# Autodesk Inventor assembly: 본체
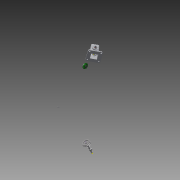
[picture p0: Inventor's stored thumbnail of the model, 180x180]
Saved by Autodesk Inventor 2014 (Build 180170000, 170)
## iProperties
Created: 2016-02
Part Number: 본체
Document SubType Name: Assembly
Designer: user
Author: user
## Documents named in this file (15)
- C:\Users\user\Desktop\460212V1001\본체.iam
- C:\Users\user\Desktop\460212V1001\본체1.ipt
- C:\Users\user\Desktop\460212V1001\편심축.ipt
- C:\Users\user\Desktop\460212V1001\V벨트풀리.ipt
- C:\Users\user\Desktop\460212V1001\고정핀 1.2 x 10.ipt
- C:\Users\user\Desktop\460212V1001\링크.ipt
- C:\Users\user\Desktop\460212V1001\멈춤나사 M3x8.ipt
- C:\Users\user\Desktop\460212V1001\베어링 12 x 32 x 10.ipt
- C:\Users\user\Desktop\460212V1001\볼트 M4 x 12.ipt
- C:\Users\user\Desktop\460212V1001\부시.ipt
- C:\Users\user\Desktop\460212V1001\슬라이드.ipt
- C:\Users\user\Desktop\460212V1001\앞커버.ipt
- C:\Users\user\Desktop\460212V1001\오일실 12 25 7.ipt
- C:\Users\user\Desktop\460212V1001\키 4 x 4 x 10.ipt
- C:\Users\user\Desktop\460212V1001\핀 5 x 18.ipt
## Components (4 placed, 4 different names)
1. V벨트풀리:1 — Mate:3, Mate:15, Mate:16, Mate:17, Mate:18, Mate:19, Mate:20
2. 고정핀 1.2 x 10:1 — Mate:12, Tangent:1
3. ISO 4762 M4 x 12:1
4. 핀 5 x 18:1 — Mate:10, Mate:11, Mate:12, Tangent:1
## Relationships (11: Mate 10, Tangent 1)
- Mate:3: V벨트풀리:1
- Mate:10: 핀 5 x 18:1
- Mate:11: 핀 5 x 18:1
- Mate:12: 고정핀 1.2 x 10:1 ↔ 핀 5 x 18:1
- Tangent:1: 고정핀 1.2 x 10:1 ↔ 핀 5 x 18:1
- Mate:15: V벨트풀리:1
- Mate:16: V벨트풀리:1
- Mate:17: V벨트풀리:1
- Mate:18: V벨트풀리:1
- Mate:19: V벨트풀리:1
- Mate:20: V벨트풀리:1
